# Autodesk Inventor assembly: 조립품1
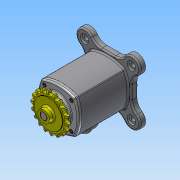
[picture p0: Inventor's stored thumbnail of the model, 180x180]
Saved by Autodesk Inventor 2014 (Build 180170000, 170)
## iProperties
Created: 2016-05
Part Number: 조립품1
Document SubType Name: Assembly
Designer: NET
Author: NET
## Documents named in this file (11)
- C:\Users\NET\Desktop\460507v1010\조립품1.iam
- C:\Users\NET\Desktop\460507v1010\본체.ipt
- C:\Users\NET\Desktop\460507v1010\편심축.ipt
- C:\Users\NET\Desktop\460507v1010\키5x5.ipt
- C:\Users\NET\Desktop\460507v1010\스프로킷.ipt
- C:\Users\NET\Desktop\460507v1010\베어링-6203.ipt
- C:\Users\NET\Desktop\460507v1010\커버.ipt
- C:\Users\NET\Desktop\460507v1010\오일실.ipt
- C:\Users\NET\Desktop\460507v1010\슬라이더.ipt
- C:\Users\NET\Desktop\460507v1010\부시.ipt
- C:\Users\NET\Desktop\460507v1010\M4x0.7x12.ipt
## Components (8 placed, 1 different names)
1. M4x0.7x12:1
2. M4x0.7x12:3
3. M4x0.7x12:4
4. M4x0.7x12:5
5. M4x0.7x12:2
6. M4x0.7x12:6
7. M4x0.7x12:7
8. M4x0.7x12:8
